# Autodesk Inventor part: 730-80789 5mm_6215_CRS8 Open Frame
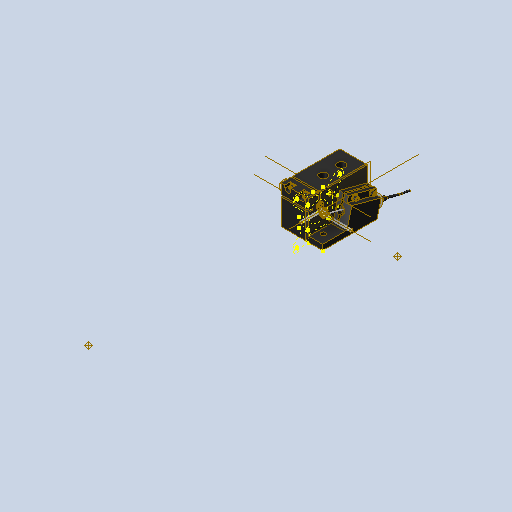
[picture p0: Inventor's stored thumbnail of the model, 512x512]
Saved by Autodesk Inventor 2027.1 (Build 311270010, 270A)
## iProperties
Created: 2014-04
Part Number: 730-80789 5mm_6215_CRS8 Open Frame
Material: Generic
Description: STEP AP203
Document SubType Name: Modeling
Designer: Radek
Density: 1 g/cm^3
Appearance: Default
Sending System: SolidWorks 2011
Preprocessor: SwSTEP 2.0
Title: 730-80789 4mm_6215_CRS8 Open Frame.STEP
Revision Number: ANY
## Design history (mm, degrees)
feature "Composite1"
sketch "Sketch1"
  geometry: 5 further points
  constraints: 1 vertical alignment, 1 other
workaxis "Work Axis1"
workaxis "Work Axis2"
workplane "Work Plane1"
workpoint "Work Point1"
workpoint "Work Point2"
workaxis "Work Axis3"
workaxis "Work Axis4"
sketch "Sketch4"
  geometry: C1 r 2 at (0, 0) reference; 1 further point
extrude "Extrusion1" new body sketch "Sketch4" distance "d1" = 65; taper "d2" = 0 deg
sketch "Sketch5"
  geometry: C1 r 2 at (0, 0) reference; 1 further point
extrude "Extrusion2" join sketch "Sketch5" distance "d3" = 300; taper "d4" = 0 deg
workpoint "Work Point3"
workplane "Work Plane2"
  workpoint "Work Point4"
workplane "Work Plane3"
body "Solid1"
node "Finishes"
sketch "Sketch3"
  geometry: L1 (9.561, -28.496)-(22.687, -41.622) reference; L2 (22.687, -41.622)-(30.815, -41.622) reference; L3 (30.815, -41.622)-(33.355, -39.082) reference; L4 (33.355, -30.954)-(33.355, -39.082) reference; L5 (20.229, -17.828)-(33.355, -30.954) reference; L6 (18.369, 0.706)-(18.369, -13.337) reference; L7 (20.229, 5.196)-(33.355, 18.322) reference; L8 (33.355, 26.45)-(33.355, 18.322) reference; L9 (30.815, 28.99)-(33.355, 26.45) reference; L10 (22.687, 28.99)-(30.815, 28.99) reference; L11 (9.561, 15.864)-(22.687, 28.99) reference; L12 (-8.973, 14.004)-(5.071, 14.004) reference; L13 (-13.463, 15.864)-(-26.589, 28.99) reference; L14 (-34.717, 28.99)-(-26.589, 28.99) reference; L15 (-34.717, 28.99)-(-37.257, 26.45) reference; L16 (-37.257, 26.45)-(-37.257, 18.322) reference; L17 (-24.131, 5.196)-(-37.257, 18.322) reference; L18 (-22.271, 0.706)-(-22.271, -13.337) reference; L19 (-24.131, -17.828)-(-37.257, -30.954) reference; L20 (-37.257, -30.954)-(-37.257, -39.082) reference; L21 (-37.257, -39.082)-(-34.717, -41.622) reference; L22 (-34.717, -41.622)-(-26.589, -41.622) reference; L23 (-13.463, -28.496)-(-26.589, -41.622) reference; L24 (-8.973, -26.636)-(5.071, -26.636) reference; C1 r 3.264 at (28.049, 23.684) reference; C2 r 3.264 at (13.049, 8.684) reference; C3 r 3.264 at (-16.951, 8.684) reference; C4 r 3.264 at (-31.951, 23.684) reference; C5 r 3.264 at (-31.951, -36.316) reference; C6 r 3.264 at (-16.951, -21.316) reference; C7 r 3.264 at (13.049, -21.316) reference; C8 r 3.264 at (28.049, -36.316) reference; C9 r 13.398 at (-1.951, -6.316) reference; A1 r 6.35 centre (24.719, -13.337) between (18.369, -13.337) and (20.229, -17.828) reference; A2 r 6.35 centre (24.719, 0.706) between (20.229, 5.196) and (18.369, 0.706) reference; A3 r 6.35 centre (5.071, 20.354) between (5.071, 14.004) and (9.561, 15.864) reference; A4 r 6.35 centre (-8.973, 20.354) between (-13.463, 15.864) and (-8.973, 14.004) reference; A5 r 6.35 centre (-28.621, 0.706) between (-22.271, 0.706) and (-24.131, 5.196) reference; A6 r 6.35 centre (-28.621, -13.337) between (-24.131, -17.828) and (-22.271, -13.337) reference; A7 r 6.35 centre (-8.973, -32.986) between (-8.973, -26.636) and (-13.463, -28.496) reference; A8 r 6.35 centre (5.071, -32.986) between (9.561, -28.496) and (5.071, -26.636) reference; 1 further point
node "Reference1"
body "Srf1"
node "Finish1" dims "Finish1_Area" = 94.71874
other parameters: "d0" = 0
